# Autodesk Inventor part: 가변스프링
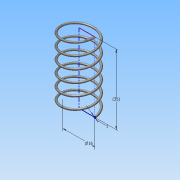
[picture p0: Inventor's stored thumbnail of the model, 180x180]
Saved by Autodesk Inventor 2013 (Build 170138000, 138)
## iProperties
Created: 2016-05
Part Number: 가변스프링
Material: 스테인리스강
Document SubType Name: Modeling
Designer: Administrator
Density: 8.08 g/cm^3
Mass: -0.0141844 g
Surface Area: 9.46581 cm^2
Volume: -0.0017555 cm^3
Author: Administrator
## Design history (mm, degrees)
sketch "스케치1"
  geometry: L1 (0, 0)-(8, 0); L2 (8, 0)-(8, 28.5); L3 (8, 28.5)-(0, 28.5); L4 (0, 28.5)-(0, 0); C1 r 0.5 at (8, 0)
  constraints: 8 end point, 2 parallel, 1 centre point, 1 coincident, 1 horizontal, 1 perpendicular
  dimensions: "d0" = 16 diameter of L2 L4; "d2" = 28.5 distance between parallel lines of L3 L1 (derived); "d3" = 1 diameter of C1
feature "코일1" sketch "스케치1" pitch "d4" = 10; turns "d6" = 6; dims "d5" = 28.5 (= d2), "d7" = 0, angle "d8" = 90 deg, angle "d9" = 90 deg, "d10" = 0, "d11" = 0
node "작업 평면1"
feature "분할1"
feature "분할2"
node "솔리드1"
other parameters: "d12" = 90 deg
